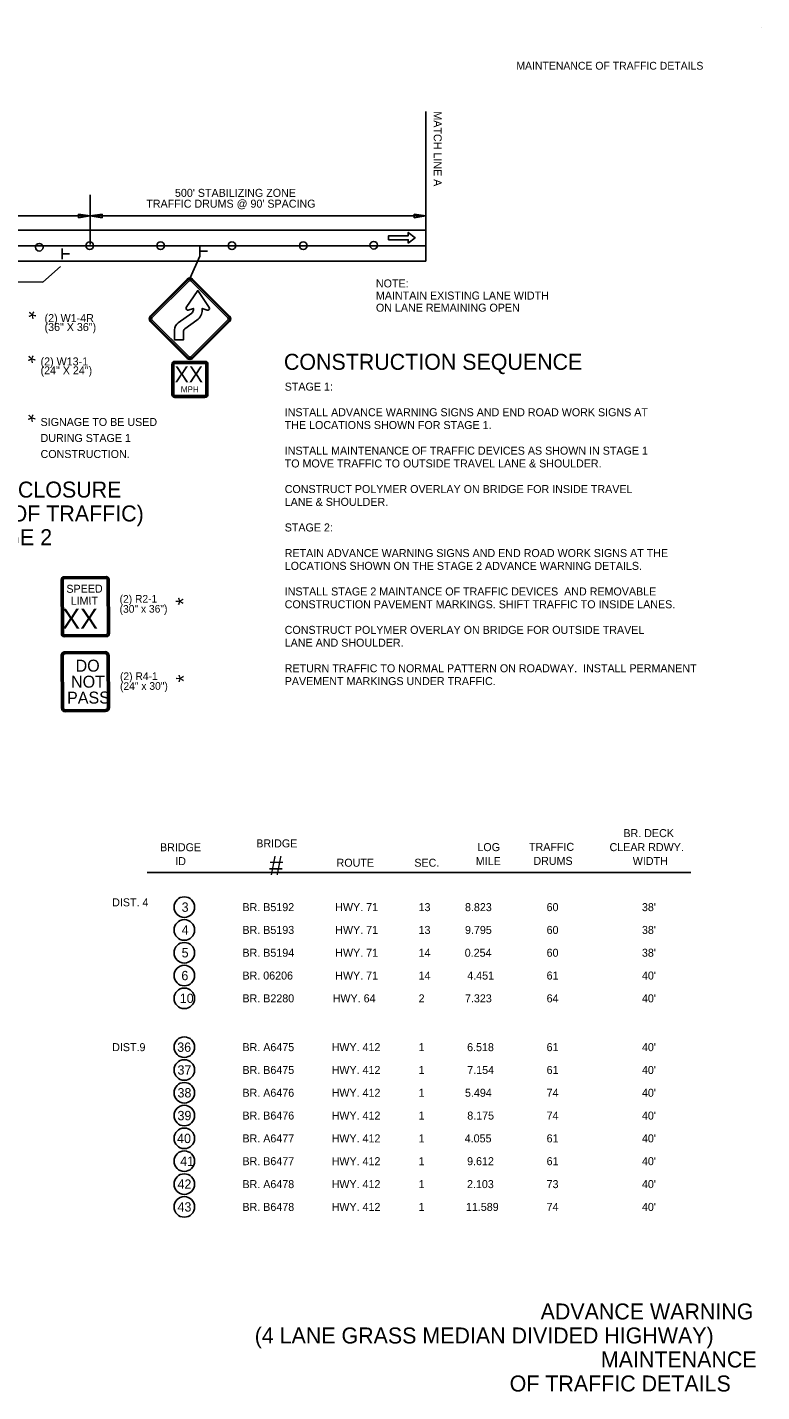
# Model space of a CAD drawing. Extents: x 1930579 to 1938222, y 596452 to 597559.
# Drawn here: x 1937672 to 1938222, y 596536 to 597559 of the extents above; entities that cross this region are included whole.
import ezdxf

# ---------------------------------------------------------------- set-up
doc = ezdxf.new("R2010")
doc.units = 0
for name, color, linetype in [('Default', 7, 'Continuous'), ('P_TC_Signs_Permanent', 7, 'Continuous'), ('R_Border', 7, 'Continuous'), ('R_Striping', 7, 'Continuous'), ('S_AREA_CALC', 7, 'Continuous')]:
    doc.layers.add(name, color=color, linetype=linetype)

msp = doc.modelspace()

# ---------------------------------------------------------------- linework, layer by layer
at = {"layer": 'Default'}
for p, q in [((1937970.5, 597495.8), (1937970.5, 597383.6)), ((1937718.7, 597433.3), (1937718.7, 597396)), ((1937718.7, 597417.4), (1937351.5, 597417.4)), ((1937709.9, 597416.1), (1937709.9, 597418.8)), ((1937709.9, 597418.8), (1937718.7, 597417.4)), ((1937718.7, 597417.4), (1937709.9, 597416.1)), ((1937718.7, 597417.4), (1937727.6, 597418.8)), ((1937970.5, 597417.4), (1937718.7, 597417.4)), ((1937727.6, 597416.1), (1937718.7, 597417.4)), ((1937727.6, 597418.8), (1937727.6, 597416.1)), ((1937961.6, 597416.1), (1937961.6, 597418.8)), ((1937961.6, 597418.8), (1937970.5, 597417.4)), ((1937970.5, 597417.4), (1937961.6, 597416.1)), ((1937970.5, 597406.7), (1937351.5, 597406.7)), ((1937970.5, 597395.1), (1936683.8, 597395.1)), ((1937697.7, 597385), (1937697.7, 597392.9)), ((1937801, 597387.2), (1937801, 597395.1)), ((1937970.5, 597383.6), (1937351.5, 597383.6)), ((1937697.8, 597388.9), (1937703.3, 597388.9)), ((1937801.1, 597391.1), (1937806.6, 597391.1))]:
    msp.add_line(p, q, dxfattribs=at)
for centre, radius in [((1937680.5, 597393.9), 2.87), ((1937718.4, 597395.1), 2.87), ((1937771.5, 597395.1), 2.87), ((1937825, 597395.1), 2.87), ((1937878.5, 597395.1), 2.87), ((1937931.4, 597395.4), 2.87), ((1937789.3, 596899.1), 7.71), ((1937789.3, 596882), 7.71), ((1937789.3, 596864.9), 7.71), ((1937789.3, 596847.8), 7.71), ((1937789.3, 596830.7), 7.71), ((1937789.3, 596794.1), 7.71), ((1937789.3, 596777), 7.71), ((1937789.3, 596759.9), 7.71), ((1937789.3, 596742.8), 7.71), ((1937789.3, 596725.7), 7.71), ((1937789.3, 596708.6), 7.71), ((1937789.3, 596691.4), 7.71), ((1937789.3, 596674.3), 7.71)]:
    msp.add_circle(centre, radius, dxfattribs=at)
at = {"layer": 'P_TC_Signs_Permanent'}
for p, q in [((1937763.7, 597342.3), (1937791.5, 597370.1)), ((1937764.2, 597341.8), (1937792.1, 597369.6)), ((1937792.9, 597368.8), (1937765, 597341)), ((1937822, 597341), (1937794.2, 597368.8)), ((1937795, 597369.6), (1937822.8, 597341.8)), ((1937795.5, 597370.1), (1937823.3, 597342.3)), ((1937784.8, 597337.2), (1937795, 597344.6)), ((1937791.5, 597310.5), (1937763.7, 597338.3)), ((1937792.1, 597311), (1937764.2, 597338.8)), ((1937765, 597339.6), (1937792.9, 597311.8)), ((1937798.8, 597339.3), (1937789.8, 597332.7)), ((1937794.2, 597311.8), (1937822, 597339.6)), ((1937822.8, 597338.8), (1937795, 597311)), ((1937823.3, 597338.3), (1937795.5, 597310.5)), ((1937780, 597306.1), (1937780, 597283.6)), ((1937780.6, 597306.1), (1937780.6, 597283.6)), ((1937781.5, 597306.1), (1937781.5, 597283.6)), ((1937804.8, 597308.3), (1937782.3, 597308.3)), ((1937804.8, 597307.8), (1937782.3, 597307.8)), ((1937804.8, 597306.8), (1937782.3, 597306.8)), ((1937805.5, 597283.6), (1937805.5, 597306.1)), ((1937806.5, 597283.6), (1937806.5, 597306.1)), ((1937807, 597283.6), (1937807, 597306.1)), ((1937782.3, 597282.8), (1937804.8, 597282.8)), ((1937782.3, 597281.9), (1937804.8, 597281.9)), ((1937782.3, 597281.3), (1937804.8, 597281.3)), ((1937730.7, 597147), (1937699.2, 597146.8)), ((1937730.7, 597146.4), (1937699.2, 597146.3)), ((1937696.9, 597144.6), (1937697.2, 597104.1)), ((1937697.5, 597144.6), (1937697.7, 597104.1)), ((1937698.4, 597144.6), (1937698.7, 597104.1)), ((1937730.7, 597145.5), (1937699.2, 597145.3)), ((1937731.7, 597104.2), (1937731.4, 597144.7)), ((1937732.6, 597104.3), (1937732.4, 597144.8)), ((1937733.2, 597104.3), (1937732.9, 597144.8)), ((1937699.4, 597103.3), (1937730.9, 597103.5)), ((1937699.4, 597102.4), (1937730.9, 597102.6)), ((1937699.4, 597101.8), (1937730.9, 597102)), ((1937696.9, 597087.6), (1937697.1, 597048.6)), ((1937697.5, 597087.6), (1937697.7, 597048.6)), ((1937698.4, 597087.6), (1937698.6, 597048.6)), ((1937729.9, 597090.7), (1937699.9, 597090.6)), ((1937729.9, 597090.1), (1937699.9, 597090)), ((1937729.9, 597089.2), (1937699.9, 597089.1)), ((1937731.6, 597048.8), (1937731.4, 597087.8)), ((1937732.5, 597048.8), (1937732.3, 597087.8)), ((1937733.1, 597048.8), (1937732.9, 597087.8)), ((1937700.2, 597047.1), (1937730.2, 597047.2)), ((1937700.2, 597046.2), (1937730.2, 597046.3)), ((1937700.2, 597045.6), (1937730.2, 597045.7))]:
    msp.add_line(p, q, dxfattribs=at)
for points in [[(1937790.8, 597348.8), (1937799.4, 597361.4), (1937808, 597348.8)], [(1937796.1, 597346.9), (1937796.1, 597348.1), (1937792.3, 597346.8)], [(1937806.5, 597346.8), (1937802.7, 597348.1), (1937802.7, 597346.9)], [(1937788.6, 597330.5), (1937788.6, 597324.4), (1937782, 597324.4), (1937782, 597331.9)]]:
    msp.add_lwpolyline(points, dxfattribs=at)
for centre, radius, start, end in [((1937793.5, 597368.1), 2.81, 45, 135), ((1937793.5, 597368.1), 2.06, 45, 135), ((1937793.5, 597368.1), 0.937, 45, 135), ((1937765.7, 597340.3), 2.81, 135, 225), ((1937765.7, 597340.3), 2.06, 135, 225), ((1937765.7, 597340.3), 0.937, 135, 225), ((1937791.9, 597348.1), 1.31, 145.6763, 287.8128), ((1937793.3, 597346.9), 2.81, 305.7733, 0), ((1937793.3, 597346.9), 9.37, 305.7733, 0), ((1937806.9, 597348.1), 1.31, 252.1872, 34.3237), ((1937821.4, 597340.3), 0.937, 315, 45), ((1937821.4, 597340.3), 2.06, 315, 45), ((1937821.4, 597340.3), 2.81, 315, 45), ((1937788.6, 597331.9), 6.56, 125.7733, 180), ((1937791.4, 597330.5), 2.81, 125.7733, 180), ((1937793.5, 597312.5), 2.81, 225, 315), ((1937793.5, 597312.5), 2.06, 225, 315), ((1937793.5, 597312.5), 0.937, 225, 315), ((1937782.3, 597306.1), 2.25, 90, 180), ((1937782.3, 597306.1), 1.69, 90, 180), ((1937782.3, 597306.1), 0.75, 90, 180), ((1937804.8, 597306.1), 2.25, 360, 90), ((1937804.8, 597306.1), 1.69, 360, 90), ((1937804.8, 597306.1), 0.75, 360, 90), ((1937782.3, 597283.6), 2.25, 180, 270), ((1937782.3, 597283.6), 1.69, 180, 270), ((1937782.3, 597283.6), 0.75, 180, 270), ((1937804.8, 597283.6), 2.25, 270, 360), ((1937804.8, 597283.6), 1.69, 270, 360), ((1937804.8, 597283.6), 0.75, 270, 360), ((1937699.2, 597144.6), 2.25, 90.312, 180.312), ((1937699.2, 597144.6), 1.69, 90.312, 180.312), ((1937730.7, 597144.7), 2.25, 0.312, 90.312), ((1937730.7, 597144.7), 1.69, 0.312, 90.312), ((1937699.2, 597144.6), 0.75, 90.312, 180.312), ((1937730.7, 597144.7), 0.75, 0.312, 90.312), ((1937699.4, 597104.1), 2.25, 180.312, 270.312), ((1937699.4, 597104.1), 1.69, 180.312, 270.312), ((1937699.4, 597104.1), 0.75, 180.312, 270.312), ((1937730.9, 597104.2), 2.25, 270.312, 0.312), ((1937730.9, 597104.2), 1.69, 270.312, 0.312), ((1937730.9, 597104.2), 0.75, 270.312, 0.312), ((1937699.9, 597087.6), 3, 90.312, 180.312), ((1937699.9, 597087.6), 2.4, 90.312, 180.312), ((1937699.9, 597087.6), 1.5, 90.312, 180.312), ((1937729.9, 597087.7), 3, 0.312, 90.312), ((1937729.9, 597087.7), 2.4, 0.312, 90.312), ((1937729.9, 597087.7), 1.5, 0.312, 90.312), ((1937700.1, 597048.6), 3, 180.312, 270.312), ((1937700.1, 597048.6), 2.4, 180.312, 270.312), ((1937700.1, 597048.6), 1.5, 180.312, 270.312), ((1937730.1, 597048.7), 3, 270.312, 0.312), ((1937730.1, 597048.7), 2.4, 270.312, 0.312), ((1937730.1, 597048.7), 1.5, 270.312, 0.312)]:
    msp.add_arc(centre, radius, start, end, dxfattribs=at)
at = {"layer": 'R_Border'}
for p, q in [((1937801, 597387.2), (1937793.7, 597371)), ((1937761.5, 596925), (1938169.2, 596925))]:
    msp.add_line(p, q, dxfattribs=at)
msp.add_lwpolyline([(1937475.5, 597376), (1937487.3, 597369.1), (1937566.5, 597369.1), (1937567.2, 597360.7), (1937570, 597368.4), (1937683.2, 597367.7), (1937696.4, 597379.5)], dxfattribs=at)
at = {"layer": 'R_Striping'}
msp.add_lwpolyline([(1937957.2, 597397), (1937962.4, 597401), (1937957.2, 597405), (1937957.2, 597402.5), (1937942.5, 597402.5), (1937942.5, 597399.5), (1937957.2, 597399.5)], close=True, dxfattribs=at)
at = {"layer": 'S_AREA_CALC'}
msp.add_line((1938222.3, 597558.9), (1938222.3, 597558.9), dxfattribs=at)

# ---------------------------------------------------------------- texts
at = {"layer": 'Default'}
for s, height, rotation, p in [('MATCH LINE A', 6, 270, (1937976.3, 597495.8)), ("500' STABILIZING ZONE", 6, 360, (1937782.3, 597431.7)), ("TRAFFIC DRUMS @ 90' SPACING ", 6, 360, (1937760.8, 597423.6)), ('RIGHT LANE CLOSURE ', 12, 360, (1937563.8, 597206.2)), ('(IN DIRECTION OF TRAFFIC)', 12, 360, (1937540.5, 597188.3)), ('STAGE 2', 12, 360, (1937622.4, 597170.5))]:
    msp.add_text(s, height=height, rotation=rotation, dxfattribs=at).set_placement(p)
at = {"layer": 'P_TC_Signs_Permanent'}
for s, height, rotation, p in [('XX', 12, 360, (1937782, 597292.6)), ('MPH', 4.5, 360, (1937786.7, 597285.1)), ('SPEED', 6, 0.312, (1937700.9, 597134.8)), ('LIMIT', 6, 0.312, (1937704.1, 597125.8)), ('XX', 15, 0.312, (1937697.8, 597107.8)), ('DO', 9, 0.312, (1937707.8, 597075.6)), ('NOT', 9, 0.2716, (1937704.4, 597063.6)), ('PASS', 9, 0.312, (1937701.4, 597051.6))]:
    msp.add_text(s, height=height, rotation=rotation, dxfattribs=at).set_placement(p)
at = {"layer": 'R_Border'}
for s, height, rotation, p in [('NOTE:', 6, 360, (1937933, 597363.8)), ('MAINTAIN EXISTING LANE WIDTH ', 6, 360, (1937933, 597354.7)), ('ON LANE REMAINING OPEN', 6, 360, (1937933, 597345.6)), ('*', 11.5, 45, (1937679.1, 597335)), ('(2) W1-4R', 6, 360, (1937684.5, 597337.8)), ('(36" X 36")', 6, 360, (1937684.5, 597331.1)), ('*', 11.5, 45, (1937678.6, 597302)), ('(2) W13-1', 6, 360, (1937681.5, 597305.3)), ('CONSTRUCTION SEQUENCE', 12, 360, (1937864, 597302)), ('(24" X 24")', 6, 360, (1937681.5, 597298.6)), ('STAGE 1:', 6, 360, (1937864.6, 597286.4)), ('*', 11.5, 45, (1937678.6, 597257.8)), ('INSTALL ADVANCE WARNING SIGNS AND END ROAD WORK SIGNS AT', 6, 360, (1937864.6, 597267.2)), ('SIGNAGE TO BE USED', 6, 360, (1937681.5, 597259.9)), ('THE LOCATIONS SHOWN FOR STAGE 1.', 6, 360, (1937864.6, 597257.6)), ('DURING STAGE 1', 6, 360, (1937681.5, 597247.9)), ('CONSTRUCTION.', 6, 360, (1937681.5, 597235.9)), ('INSTALL MAINTENANCE OF TRAFFIC DEVICES AS SHOWN IN STAGE 1', 6, 360, (1937864.6, 597238.4)), ('TO MOVE TRAFFIC TO OUTSIDE TRAVEL LANE & SHOULDER.', 6, 360, (1937864.6, 597228.8)), ('CONSTRUCT POLYMER OVERLAY ON BRIDGE FOR INSIDE TRAVEL', 6, 360, (1937864.6, 597209.6)), ('LANE & SHOULDER.', 6, 360, (1937864.6, 597200)), ('STAGE 2:', 6, 360, (1937864.6, 597180.8)), ('RETAIN ADVANCE WARNING SIGNS AND END ROAD WORK SIGNS AT THE', 6, 360, (1937864.6, 597161.6)), ('LOCATIONS SHOWN ON THE STAGE 2 ADVANCE WARNING DETAILS.', 6, 360, (1937864.6, 597152)), ('INSTALL STAGE 2 MAINTANCE OF TRAFFIC DEVICES  AND REMOVABLE', 6, 360, (1937864.6, 597132.8)), ('(2) R2-1', 5.76, 0.312, (1937740.8, 597127.3)), ('(30" x 36")', 5.76, 0.312, (1937740.8, 597119.8)), ('*', 11.5, 90.312, (1937794.4, 597125.5)), ('CONSTRUCTION PAVEMENT MARKINGS. SHIFT TRAFFIC TO INSIDE LANES.', 6, 360, (1937864.6, 597123.2)), ('CONSTRUCT POLYMER OVERLAY ON BRIDGE FOR OUTSIDE TRAVEL', 6, 360, (1937864.6, 597104)), ('LANE AND SHOULDER.', 6, 360, (1937864.6, 597094.4)), ('(2) R4-1', 5.76, 0.312, (1937741.1, 597069.3)), ('RETURN TRAFFIC TO NORMAL PATTERN ON ROADWAY.  INSTALL PERMANENT', 6, 360, (1937864.6, 597075.2)), ('(24" x 30")', 5.76, 0.312, (1937741.1, 597061.9)), ('*', 11.5, 90.312, (1937794.7, 597067.6)), ('PAVEMENT MARKINGS UNDER TRAFFIC.', 6, 360, (1937864.6, 597065.6)), ('BR. DECK ', 6, 360, (1938118.6, 596951.6)), ('BRIDGE ', 6, 360, (1937771.1, 596941)), ('BRIDGE ', 6, 360, (1937843.3, 596943.9)), ('LOG', 6, 360, (1938009.1, 596941.1)), ('TRAFFIC ', 6, 360, (1938047.8, 596941.3)), ('CLEAR RDWY.', 6, 360, (1938108.2, 596941.1)), ('ID', 6, 360, (1937782.5, 596930.6)), ('#', 14.2, 360, (1937852.9, 596923.2)), ('ROUTE', 6, 360, (1937903.5, 596929.4)), ('SEC.', 6, 360, (1937961.8, 596929.4)), ('MILE', 6, 360, (1938007.9, 596930.6)), ('DRUMS', 6, 360, (1938051.1, 596930.8)), ('WIDTH', 6, 360, (1938125.6, 596930.7)), ('DIST. 4', 6, 360, (1937735.2, 596899.7)), ('3', 7, 360, (1937787.3, 596895.6)), ('BR. B5192', 6, 360, (1937832.9, 596896.1)), ('HWY. 71', 6, 360, (1937902.5, 596896.1)), ('13', 6, 360, (1937965, 596896.1)), ('8.823', 6, 360, (1937999.8, 596896.1)), ('60', 6, 360, (1938061, 596896.1)), ("38'", 6, 360, (1938132.5, 596896.1)), ('4', 7, 360, (1937787.3, 596878.5)), ('BR. B5193', 6, 360, (1937832.9, 596879)), ('HWY. 71', 6, 360, (1937902.5, 596879)), ('13', 6, 360, (1937965, 596879)), ('9.795', 6, 360, (1937999.8, 596879)), ('60', 6, 360, (1938061, 596879)), ("38'", 6, 360, (1938132.5, 596879)), ('5', 7, 360, (1937787.3, 596861.4)), ('BR. B5194', 6, 360, (1937832.9, 596861.9)), ('HWY. 71', 6, 360, (1937902.5, 596861.9)), ('14', 6, 360, (1937965, 596861.9)), ('0.254', 6, 360, (1937999.6, 596861.9)), ('60', 6, 360, (1938061, 596861.9)), ("38'", 6, 360, (1938132.5, 596861.9)), ('6', 7, 360, (1937787.1, 596844.3)), ('BR. 06206', 6, 360, (1937832.9, 596844.8)), ('HWY. 71', 6, 360, (1937902.5, 596844.8)), ('14', 6, 360, (1937965, 596844.8)), ('4.451', 6, 360, (1938001.5, 596844.8)), ('61', 6, 360, (1938061, 596844.8)), ("40'", 6, 360, (1938132.5, 596844.8)), ('10', 7, 360, (1937785.9, 596827.2)), ('BR. B2280', 6, 360, (1937832.9, 596827.7)), ('HWY. 64', 6, 360, (1937900.6, 596827.7)), ('2', 6, 360, (1937965, 596827.7)), ('7.323', 6, 360, (1937999.8, 596827.7)), ('64', 6, 360, (1938061, 596827.7)), ("40'", 6, 360, (1938132.5, 596827.7)), ('DIST.9', 6, 360, (1937735.2, 596791.1)), ('36', 7, 360, (1937784, 596790.6)), ('BR. A6475', 6, 360, (1937832.9, 596791.1)), ('HWY. 412', 6, 360, (1937899.8, 596791.1)), ('1', 6, 360, (1937965, 596791.1)), ('6.518', 6, 360, (1938001.4, 596791.1)), ('61', 6, 360, (1938061, 596791.1)), ("40'", 6, 360, (1938132.5, 596791.1)), ('37', 7, 360, (1937784.2, 596773.5)), ('BR. B6475', 6, 360, (1937832.9, 596774)), ('HWY. 412', 6, 360, (1937899.8, 596774)), ('1', 6, 360, (1937965, 596774)), ('7.154', 6, 360, (1938001.5, 596774)), ('61', 6, 360, (1938061, 596774)), ("40'", 6, 360, (1938132.5, 596774)), ('38', 7, 360, (1937784.2, 596756.4)), ('BR. A6476', 6, 360, (1937832.9, 596756.9)), ('HWY. 412', 6, 360, (1937899.8, 596756.9)), ('1', 6, 360, (1937965, 596756.9)), ('5.494', 6, 360, (1937999.8, 596756.9)), ('74', 6, 360, (1938061, 596756.9)), ("40'", 6, 360, (1938132.5, 596756.9)), ('39', 7, 360, (1937784.2, 596739.3)), ('BR. B6476', 6, 360, (1937832.9, 596739.8)), ('HWY. 412', 6, 360, (1937899.8, 596739.8)), ('1', 6, 360, (1937965, 596739.8)), ('8.175', 6, 360, (1938001.5, 596739.8)), ('74', 6, 360, (1938061, 596739.8)), ("40'", 6, 360, (1938132.5, 596739.8)), ('40', 7, 360, (1937783.9, 596722.2)), ('BR. A6477', 6, 360, (1937832.9, 596722.7)), ('HWY. 412', 6, 360, (1937899.8, 596722.7)), ('1', 6, 360, (1937965, 596722.7)), ('4.055', 6, 360, (1937999.6, 596722.7)), ('61', 6, 360, (1938061, 596722.7)), ("40'", 6, 360, (1938132.5, 596722.7)), ('41', 7, 360, (1937786.2, 596705.1)), ('BR. B6477', 6, 360, (1937832.9, 596705.6)), ('HWY. 412', 6, 360, (1937899.8, 596705.6)), ('1', 6, 360, (1937965, 596705.6)), ('9.612', 6, 360, (1938001.4, 596705.6)), ('61', 6, 360, (1938061, 596705.6)), ("40'", 6, 360, (1938132.5, 596705.6)), ('42', 7, 360, (1937784.2, 596687.9)), ('BR. A6478', 6, 360, (1937832.9, 596688.4)), ('HWY. 412', 6, 360, (1937899.8, 596688.4)), ('1', 6, 360, (1937965, 596688.4)), ('2.103', 6, 360, (1938001.3, 596688.4)), ('73', 6, 360, (1938061, 596688.4)), ("40'", 6, 360, (1938132.5, 596688.4)), ('43', 7, 360, (1937784.2, 596670.8)), ('BR. B6478', 6, 360, (1937832.9, 596671.3)), ('HWY. 412', 6, 360, (1937899.8, 596671.3)), ('1', 6, 360, (1937965, 596671.3)), ('11.589', 6, 360, (1938000.5, 596671.3)), ('74', 6, 360, (1938061, 596671.3)), ("40'", 6, 360, (1938132.5, 596671.3)), ('ADVANCE WARNING ', 12, 360, (1938056.5, 596589.9)), ('(4 LANE GRASS MEDIAN DIVIDED HIGHWAY)', 12, 360, (1937842.1, 596571.9)), ('MAINTENANCE ', 12, 360, (1938101.7, 596553.9)), ('OF TRAFFIC DETAILS', 12, 360, (1938033.3, 596535.9))]:
    msp.add_text(s, height=height, rotation=rotation, dxfattribs=at).set_placement(p)
at = {"layer": 'S_AREA_CALC'}
msp.add_text('MAINTENANCE OF TRAFFIC DETAILS', height=5.862, rotation=360, dxfattribs=at).set_placement((1938038.3, 597527.1))

doc.saveas('drawing.dxf')
